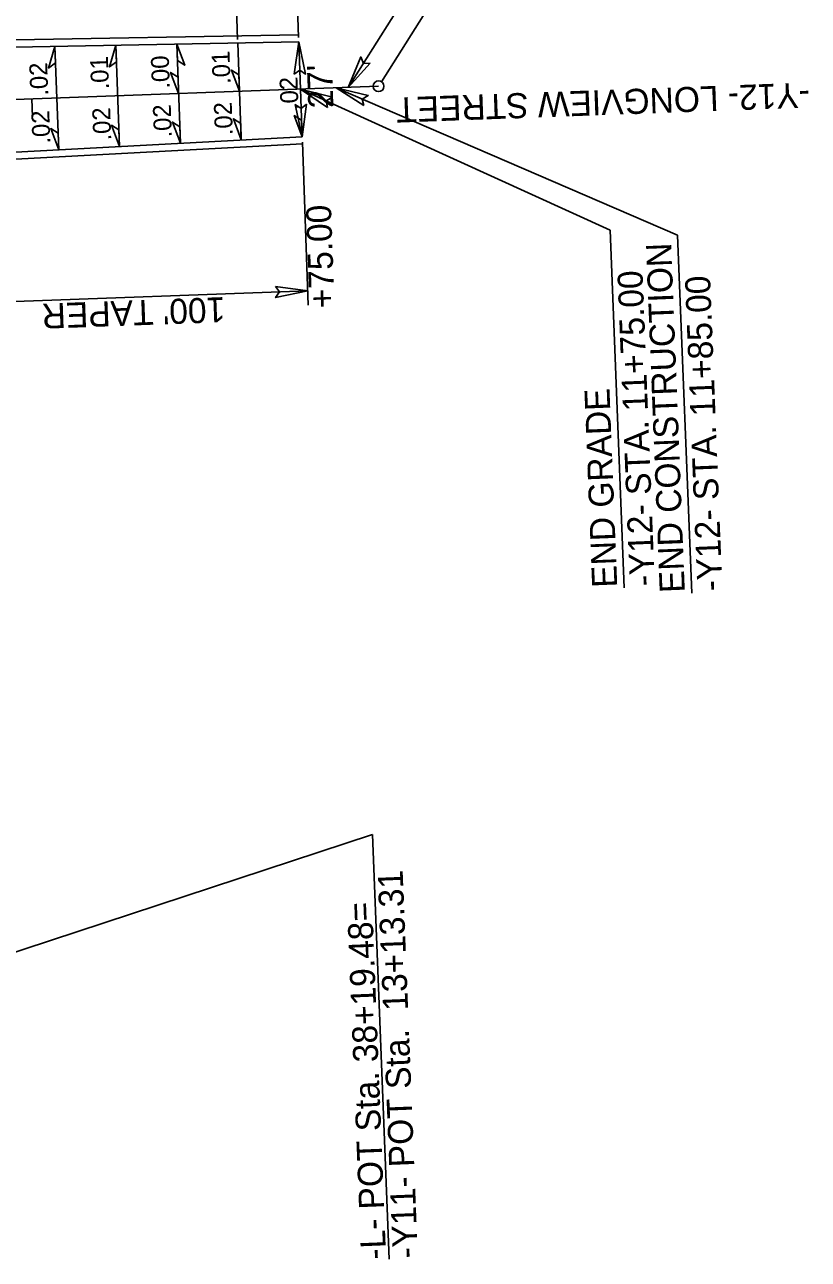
# Model space of a CAD drawing. Extents: x 1627861 to 1629601, y 761281 to 766239.
# Drawn here: x 1628487.4 to 1628706, y 764235.4 to 764580 of the extents above; entities that cross this region are included whole.
import ezdxf

# ---------------------------------------------------------------- set-up
doc = ezdxf.new("R2010")
doc.units = 0
for name, color, linetype in [('Exist Other Culture Sign Leader', 7, 'Continuous'), ('Exist Property Tie Line Text', 7, 'Continuous'), ('Exist Right of Way Line Leader', 7, 'Continuous'), ('Exist Right of Way Monument Text', 7, 'Continuous'), ('Exist Utilities Gas Meter CELL', 7, 'Continuous'), ('Exist Utilities Gas Meter Cogo Number', 7, 'Continuous'), ('Exist Utilities Power UG Cable SUE LOS B Cogo Point CELL', 7, 'Continuous'), ('Exist Utilities Telephone UG Cable SUE LOS B Cogo Point CELL', 7, 'Continuous'), ('Exist Utilities Water UG Line SUE LOS B Cogo Number', 7, 'Continuous'), ('Scratch_Level_0', 7, 'Continuous'), ('Typical Terminator CELL', 7, 'Continuous')]:
    doc.layers.add(name, color=color, linetype=linetype)

msp = doc.modelspace()

# ---------------------------------------------------------------- linework, layer by layer
at = {"layer": 'Exist Property Tie Line Text'}
msp.add_line((1628489.41, 764559.27), (1628489.59, 764554.28), dxfattribs=at)
at = {"layer": 'Exist Right of Way Line Leader'}
for p, q in [((1628586.95, 764564.08), (1628635.55, 764641.16)), ((1628577.69, 764562.5), (1628620.22, 764629.95)), ((1628401.25, 764293.68), (1628584.48, 764353.98)), ((1628589.15, 764235.39), (1628584.48, 764353.98))]:
    msp.add_line(p, q, dxfattribs=at)
msp.add_circle((1628586.15, 764562.81), 1.5, dxfattribs=at)
at = {"layer": 'Exist Right of Way Monument Text'}
for p, q in [((1628463.87, 764573.35), (1628563.87, 764575.2)), ((1628464.97, 764543.37), (1628564.84, 764548.72))]:
    msp.add_line(p, q, dxfattribs=at)
at = {"layer": 'Exist Utilities Gas Meter CELL'}
msp.add_line((1628389.47, 764555.61), (1628586.15, 764562.81), dxfattribs=at)
msp.add_line((1628389.47, 764555.61), (1628586.15, 764562.81), dxfattribs=at)
at = {"layer": 'Exist Utilities Gas Meter Cogo Number'}
for points in [[(1628562.65, 764566.15), (1628563.87, 764575.2), (1628565.8, 764566.22), (1628564.16, 764567.31)], [(1628583.81, 764569.29), (1628577.69, 764562.5), (1628581.17, 764571.01), (1628581.91, 764569.19)], [(1628571.9, 764556.87), (1628564.36, 764562.02), (1628573.26, 764559.72), (1628571.55, 764558.74)], [(1628582, 764557.39), (1628574.35, 764562.38), (1628583.29, 764560.26), (1628581.6, 764559.25)], [(1628566.06, 764557.77), (1628564.84, 764548.72), (1628562.91, 764557.71), (1628564.55, 764556.62)], [(1628557.37, 764506.96), (1628566.42, 764505.74), (1628557.43, 764503.81), (1628558.52, 764505.45)]]:
    msp.add_lwpolyline(points, close=True, dxfattribs=at)
at = {"layer": 'Exist Utilities Telephone UG Cable SUE LOS B Cogo Point CELL'}
for p, q in [((1628463.84, 764575.35), (1628563.84, 764577.2)), ((1628465.08, 764541.37), (1628564.95, 764546.72))]:
    msp.add_line(p, q, dxfattribs=at)
at = {"layer": 'Exist Utilities Water UG Line SUE LOS B Cogo Number'}
for p, q in [((1628496.93, 764545.08), (1628495.87, 764573.94)), ((1628513.91, 764545.99), (1628512.87, 764574.26)), ((1628530.89, 764546.9), (1628529.87, 764574.57)), ((1628547.87, 764547.81), (1628546.87, 764574.89)), ((1628564.84, 764548.72), (1628563.87, 764575.2))]:
    msp.add_line(p, q, dxfattribs=at)
at = {"layer": 'Scratch_Level_0'}
for p, q in [((1628546.84, 764575.83), (1628545.21, 764620.35)), ((1628563.83, 764576.4), (1628562.21, 764620.66)), ((1628564.84, 764548.72), (1628563.87, 764575.2)), ((1628564.36, 764562.02), (1628650.73, 764522.66)), ((1628574.35, 764562.38), (1628669.58, 764521.21)), ((1628566.56, 764501.73), (1628564.9, 764547.19)), ((1628650.73, 764522.66), (1628654.67, 764422.79)), ((1628669.58, 764521.21), (1628673.52, 764421.35)), ((1628466.48, 764502.08), (1628566.42, 764505.74))]:
    msp.add_line(p, q, dxfattribs=at)
at = {"layer": 'Typical Terminator CELL'}
for points in [[(1628495.87, 764573.94), (1628494.1, 764567.87), (1628496.04, 764569.32)], [(1628512.87, 764574.26), (1628511.1, 764568.19), (1628513.04, 764569.63)], [(1628529.87, 764574.57), (1628532.09, 764568.65), (1628530.04, 764569.95)], [(1628530.38, 764560.77), (1628528.16, 764566.69), (1628530.21, 764565.39)], [(1628547.37, 764561.39), (1628545.15, 764567.32), (1628547.2, 764566.02)], [(1628530.89, 764546.9), (1628528.67, 764552.82), (1628530.72, 764551.52)], [(1628547.87, 764547.81), (1628545.65, 764553.73), (1628547.7, 764552.43)], [(1628564.84, 764548.72), (1628562.62, 764554.64), (1628564.67, 764553.34)], [(1628496.93, 764545.08), (1628494.71, 764551), (1628496.76, 764549.7)], [(1628513.91, 764545.99), (1628511.69, 764551.91), (1628513.74, 764550.61)]]:
    msp.add_lwpolyline(points, close=True, dxfattribs=at)

# ---------------------------------------------------------------- texts
at = {"layer": 'Exist Other Culture Sign Leader'}
for s, rotation, p in [('-Y12- LONGVIEW STREET', 182.0964, (1628706.33, 764563.87)), ('END CONSTRUCTION', 92.2582, (1628671.6, 764421.54)), ('-Y12- STA. 11+75.00', 92.2582, (1628663.24, 764423.4)), ('-Y12- STA. 11+85.00', 92.2582, (1628682.09, 764421.96)), ("100' TAPER", 182.0964, (1628543.24, 764503.98)), ('END GRADE', 92.2582, (1628652.75, 764422.99))]:
    msp.add_text(s, height=7, rotation=rotation, dxfattribs=at).set_placement(p)
at = {"layer": 'Exist Right of Way Line Leader'}
for s, p in [('-Y11- POT Sta.  13+13.31', (1628597.14, 764235.77)), ('-L- POT Sta. 38+19.48=', (1628588.28, 764235.42))]:
    msp.add_text(s, height=7, rotation=92.2582, dxfattribs=at).set_placement(p)
at = {"layer": 'Exist Utilities Power UG Cable SUE LOS B Cogo Point CELL'}
for s, p in [("27'", (1628573.58, 764556.79)), ('+75.00', (1628573.9, 764500.98))]:
    msp.add_text(s, height=7, rotation=92.0586, dxfattribs=at).set_placement(p)
at = {"layer": 'Exist Utilities Water UG Line SUE LOS B Cogo Number'}
for s, p in [('.01', (1628510.98, 764561.99)), ('.00', (1628527.95, 764562.2)), ('.01', (1628544.89, 764563.52)), ('.02', (1628494.03, 764560.24)), ('.02', (1628563.85, 764556.23)), ('.02', (1628494.61, 764546.87)), ('.02', (1628511.6, 764547.73)), ('.02', (1628528.51, 764548.57)), ('.02', (1628545.52, 764549.21))]:
    msp.add_text(s, height=5, rotation=92.0964, dxfattribs=at).set_placement(p)

doc.saveas('drawing.dxf')
